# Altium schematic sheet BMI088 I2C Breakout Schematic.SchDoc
size A; SheetNumber: 1; SheetTotal: 1
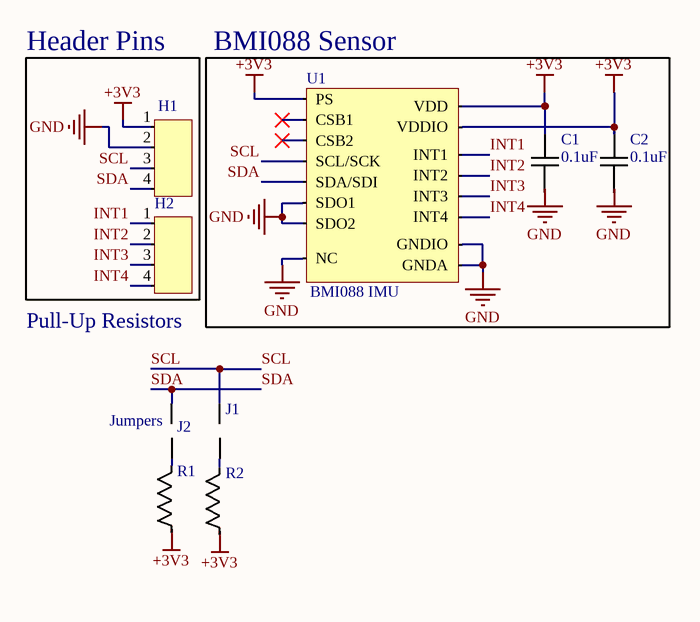
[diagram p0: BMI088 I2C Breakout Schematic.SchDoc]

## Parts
C1  0.1uF  [CL10B104KB8NNWC 0.1uF 0603-Footprint-1]
C2  0.1uF  [CL10B104KB8NNWC 0.1uF 0603-Footprint-1]
H1  PR20204VBNN 4 Pin Male Header Pin 2.54mm  [PR20204VBNN 4 Pin Male Header Pin 2.54mm-Footprint-1]  (value not drawn)
H2  PR20204VBNN 4 Pin Male Header Pin 2.54mm  [PR20204VBNN 4 Pin Male Header Pin 2.54mm-Footprint-1]  (value not drawn)
J1  Jumpers  [Small Jumper-Footprint-1]
J2  Small Jumper  [Small Jumper-Footprint-1]  (value not drawn)
R1  WR06X152 JTL 1.5K Ohm 0603  [WR06X152 JTL 1.5K Ohm 0603-Footprint-1]  (value not drawn)
R2  WR06X152 JTL 1.5K Ohm 0603  [WR06X152 JTL 1.5K Ohm 0603-Footprint-1]  (value not drawn)
U1  BMI088 IMU  [BMI088 IMU-Footprint-1]

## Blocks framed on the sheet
Header Pins: H1 H2
BMI088 Sensor: C1 C2 U1

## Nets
+3V3: C1.2 C2.2 H1.1(X) R1.1 R2.1 U1.3(VDD) U1.7(PS) U1.11(VDDIO)
GND: C1.1 C2.1 H1.2(X) U1.2(NC) U1.4(GNDA) U1.6(GNDIO) U1.10(SDO2) U1.15(SDO1)
INT1: H2.1(X) U1.16(INT1)
INT2: H2.2(X) U1.1(INT2)
INT3: H2.3(X) U1.12(INT3)
INT4: H2.4(X) U1.13(INT4)
SCL: H1.3(X) J1.1 U1.8(SCL/SCK)
SDA: H1.4(X) J2.1 U1.9(SDA/SDI)
NetJ1_2: J1.2 R2.2
NetJ2_2: J2.2 R1.2

Not connected (* = marked no-connect by the designer): U1 5(CSB2)* 14(CSB1)*

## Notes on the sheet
- (near H2) Pull-Up Resistors

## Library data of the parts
C1 C2 = CMP-00001-6: CL10B104KB8NNWC 0.1uF 0603 +-10% SMD
H1 H2 = CMP-00002-5: PR20204VBNN 4 Pin Male Header Pin 2.54mm General Use
J1 J2 = CMP-00004-3: Small Jumper For Low Current And Voltage
R1 R2 = CMP-00003-4: WR06X152 JTL 1.5K Ohm 0603 +-5% SMD
U1 = CMP-00000-17: BMI088 IMU General Use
